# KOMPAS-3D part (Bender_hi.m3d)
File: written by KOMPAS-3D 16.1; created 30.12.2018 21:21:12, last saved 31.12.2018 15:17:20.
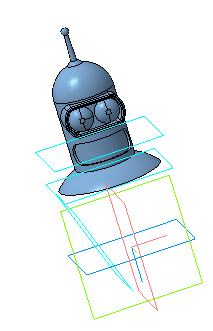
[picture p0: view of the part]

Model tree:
1. Эскиз:1
2. Операция вращения:1
     Угол 1 = 360
3. Эскиз:2
4. Операция выдавливания:1
     Расстояние 1 = 17.3; Угол 1 = 0.45
5. Скругление:1
     Радиус = 0.5
6. Скругление:2
     Радиус = 5
7. Смещенная плоскость:1
     Расстояние = 48
8. Эскиз:3
9. Вырезать элемент выдавливания:1
     Расстояние 1 = 10
10. Скругление:3
     Радиус = 5
11. Эскиз:4
12. Вырезать элемент выдавливания:2
     Расстояние 1 = 0.5
13. Эскиз:5
14. Операция вращения:2
     Угол 1 = 360
15. Эскиз:6
16. Операция вращения:3
     Угол 1 = 360
17. Эскиз:7
18. Эскиз:8
19. Кинематическая операция:1
20. Эскиз:9
21. Операция вращения:4
     Угол 1 = 360
22. Эскиз:10
23. Перпендикулярная плоскость:1
24. Эскиз:11
25. Кинематическая операция:2
26. Эскиз:12
27. Операция выдавливания:3
     Расстояние 1 = 7; Угол 1 = 20; Расстояние 2 = 0.5
28. Эскиз:13
29. Операция выдавливания:4
     Расстояние 1 = 7; Расстояние 2 = 0.5
30. Скругление:4
     Радиус = 2
31. Зеркальный массив:1
32. Экземпляр ( 1 )
33. Экземпляр ( 2 )  (with: Кинематическая операция:1, Операция вращения:4, Кинематическая операция:2, Операция выдавливания:3, Операция выдавливания:4, Скругление:4)
34. Смещенная плоскость:2
     Расстояние = 33
35. Сечение поверхностью:1

Referenced files in C:\Users\NIK\Desktop\: bender_bending_rodriguez_3d_model_c4d_max_obj_fbx_ma_lwo_3ds_3dm_stl_1135635_o.png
